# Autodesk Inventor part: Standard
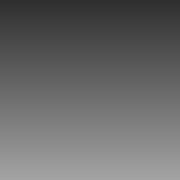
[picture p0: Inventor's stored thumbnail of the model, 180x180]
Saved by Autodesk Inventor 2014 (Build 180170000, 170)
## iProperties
Created: 2005-05
Part Number: Standard
Document SubType Name: Modeling
Designer: JWe
Density: 1 g/cm^3
Material: Generic
Appearance: Default
Author: JWe
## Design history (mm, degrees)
